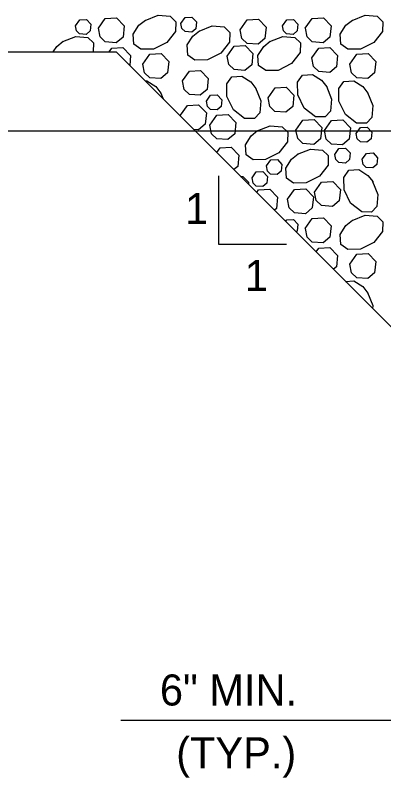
# Model space of a CAD drawing. Extents: x 2084213 to 2099800, y 976677 to 981262.
# Drawn here: x 2094470.4 to 2094587.1, y 978901.8 to 979143.3 of the extents above; entities that cross this region are included whole.
import ezdxf

# ---------------------------------------------------------------- set-up
doc = ezdxf.new("R2010")
doc.units = 0
doc.layers.add('1', color=7, linetype='Continuous')

msp = doc.modelspace()

# ---------------------------------------------------------------- linework, layer by layer
at = {"layer": '1'}
for p, q in [((2094435.37, 979131.66), (2094502.37, 979131.66)), ((2094602.37, 979031.66), (2094502.37, 979131.66)), ((2094326.82, 979106.66), (2094644.86, 979106.66)), ((2094534.73, 979092.4), (2094534.73, 979070.79)), ((2094534.73, 979070.79), (2094556.33, 979070.79)), ((2094503.83, 978919.99), (2095252.37, 978919.99))]:
    msp.add_line(p, q, dxfattribs=at)
for points in [[(2094511.5, 979141.65), (2094515.62, 979143.29), (2094519.41, 979142.96), (2094521.21, 979141.25), (2094521.16, 979138.18), (2094518.42, 979134.68), (2094514.2, 979132.57), (2094510.21, 979132.5), (2094507.97, 979134.09), (2094507.76, 979137.26), (2094509.58, 979140.1), (2094511.66, 979141.76)], [(2094522.88, 979140.68), (2094524.2, 979142.57), (2094526.32, 979142.69), (2094527.78, 979141.16), (2094527.57, 979139.03), (2094526.27, 979137.94), (2094524.18, 979138.1), (2094523.2, 979139.05), (2094522.88, 979140.68)], [(2094577.07, 979141.65), (2094581.2, 979143.29), (2094584.99, 979142.96), (2094586.79, 979141.25), (2094586.74, 979138.18), (2094584, 979134.68), (2094579.78, 979132.57), (2094575.79, 979132.5), (2094573.55, 979134.09), (2094573.34, 979137.26), (2094575.16, 979140.1), (2094577.24, 979141.76)], [(2094489.47, 979139.96), (2094490.79, 979141.84), (2094492.9, 979141.96), (2094494.37, 979140.44), (2094494.16, 979138.31), (2094492.86, 979137.22), (2094490.77, 979137.37), (2094489.79, 979138.32), (2094489.47, 979139.96)], [(2094496.7, 979139.15), (2094498.9, 979142.28), (2094502.42, 979142.49), (2094504.87, 979139.95), (2094504.52, 979136.39), (2094502.34, 979134.58), (2094498.86, 979134.83), (2094497.23, 979136.42), (2094496.7, 979139.15)], [(2094541.66, 979138.67), (2094543.87, 979141.81), (2094547.39, 979142.01), (2094549.84, 979139.47), (2094549.48, 979135.91), (2094547.31, 979134.1), (2094543.83, 979134.36), (2094542.2, 979135.94), (2094541.66, 979138.67)], [(2094555.05, 979139.96), (2094556.37, 979141.84), (2094558.48, 979141.96), (2094559.95, 979140.44), (2094559.74, 979138.31), (2094558.43, 979137.22), (2094556.35, 979137.37), (2094555.37, 979138.32), (2094555.05, 979139.96)], [(2094562.27, 979139.15), (2094564.48, 979142.28), (2094568, 979142.49), (2094570.45, 979139.95), (2094570.09, 979136.39), (2094567.92, 979134.58), (2094564.44, 979134.83), (2094562.81, 979136.42), (2094562.28, 979139.15)], [(2094528.6, 979138.27), (2094532.72, 979139.9), (2094536.51, 979139.58), (2094538.31, 979137.86), (2094538.26, 979134.79), (2094535.52, 979131.29), (2094531.3, 979129.18), (2094527.31, 979129.11), (2094525.07, 979130.7), (2094524.86, 979133.87), (2094526.68, 979136.71), (2094528.76, 979138.37)], [(2094485.43, 979134.93), (2094489.56, 979136.57), (2094493.35, 979136.24), (2094495.15, 979134.53), (2094495.1, 979131.66)], [(2094551.01, 979134.93), (2094555.14, 979136.57), (2094558.93, 979136.24), (2094560.73, 979134.53), (2094560.67, 979131.45), (2094557.94, 979127.96), (2094553.71, 979125.84), (2094549.73, 979125.77), (2094547.49, 979127.37), (2094547.28, 979130.54), (2094549.1, 979133.38), (2094551.18, 979135.04)], [(2094482.41, 979131.66), (2094483.52, 979133.38), (2094485.6, 979135.04)], [(2094500.11, 979131.66), (2094500.98, 979132.89), (2094504.5, 979133.09), (2094506.94, 979130.55), (2094506.63, 979127.4)], [(2094537.51, 979130.37), (2094539.72, 979133.51), (2094543.24, 979133.71), (2094545.69, 979131.17), (2094545.33, 979127.61), (2094543.16, 979125.8), (2094539.68, 979126.06), (2094538.05, 979127.64), (2094537.51, 979130.37)], [(2094564.35, 979129.75), (2094566.55, 979132.89), (2094570.08, 979133.09), (2094572.52, 979130.55), (2094572.17, 979127), (2094569.99, 979125.19), (2094566.52, 979125.44), (2094564.88, 979127.03), (2094564.35, 979129.75)], [(2094510.83, 979127.83), (2094513.03, 979130.97), (2094516.56, 979131.17), (2094519, 979128.63), (2094518.65, 979125.08), (2094516.47, 979123.27), (2094513, 979123.52), (2094511.36, 979125.1), (2094510.83, 979127.83)], [(2094576.41, 979127.83), (2094578.61, 979130.97), (2094582.14, 979131.17), (2094584.58, 979128.63), (2094584.23, 979125.08), (2094582.05, 979123.27), (2094578.58, 979123.52), (2094576.94, 979125.1), (2094576.41, 979127.83)], [(2094523.37, 979122.5), (2094525.58, 979125.63), (2094529.1, 979125.83), (2094531.54, 979123.3), (2094531.19, 979119.74), (2094529.01, 979117.93), (2094525.54, 979118.18), (2094523.9, 979119.77), (2094523.37, 979122.5)], [(2094546.52, 979120.28), (2094548.16, 979116.16), (2094547.83, 979112.37), (2094546.12, 979110.56), (2094543.04, 979110.62), (2094539.55, 979113.35), (2094537.44, 979117.58), (2094537.36, 979121.56), (2094538.96, 979123.8), (2094542.13, 979124.02), (2094544.97, 979122.2), (2094546.63, 979120.11)], [(2094568.94, 979120.82), (2094570.58, 979116.69), (2094570.25, 979112.9), (2094568.53, 979111.1), (2094565.46, 979111.15), (2094561.96, 979113.89), (2094559.85, 979118.11), (2094559.78, 979122.1), (2094561.37, 979124.34), (2094564.55, 979124.55), (2094567.38, 979122.73), (2094569.04, 979120.65)], [(2094511.52, 979122.51), (2094512.04, 979122.55), (2094514.88, 979120.73), (2094516.54, 979118.65)], [(2094582.02, 979118.81), (2094583.65, 979114.69), (2094583.32, 979110.9), (2094581.61, 979109.1), (2094578.54, 979109.15), (2094575.04, 979111.89), (2094572.93, 979116.11), (2094572.86, 979120.09), (2094574.45, 979122.34), (2094577.62, 979122.55), (2094580.46, 979120.73), (2094582.12, 979118.65)], [(2094516.44, 979118.81), (2094517.24, 979116.79)], [(2094550.48, 979117.16), (2094552.69, 979120.3), (2094556.21, 979120.5), (2094558.66, 979117.96), (2094558.31, 979114.4), (2094556.13, 979112.59), (2094552.65, 979112.85), (2094551.02, 979114.43), (2094550.49, 979117.16)], [(2094530.95, 979116.07), (2094532.27, 979117.95), (2094534.38, 979118.07), (2094535.85, 979116.55), (2094535.64, 979114.41), (2094534.33, 979113.33), (2094532.25, 979113.48), (2094531.27, 979114.43), (2094530.95, 979116.07)], [(2094522.75, 979111.6), (2094524.96, 979114.74), (2094528.48, 979114.94), (2094530.93, 979112.4), (2094530.57, 979108.84), (2094528.4, 979107.04), (2094526.88, 979107.15)], [(2094522.83, 979111.2), (2094522.75, 979111.6)], [(2094532.07, 979108.49), (2094534.28, 979111.62), (2094537.8, 979111.83), (2094540.25, 979109.29), (2094539.89, 979105.73), (2094537.72, 979103.92), (2094534.24, 979104.17), (2094532.6, 979105.76), (2094532.07, 979108.49)], [(2094559.31, 979106.93), (2094561.52, 979110.07), (2094565.04, 979110.27), (2094567.49, 979107.73), (2094567.13, 979104.18), (2094564.96, 979102.37), (2094561.48, 979102.62), (2094559.85, 979104.2), (2094559.31, 979106.93)], [(2094568.39, 979106.8), (2094570.59, 979109.94), (2094574.11, 979110.14), (2094576.56, 979107.6), (2094576.21, 979104.04), (2094574.03, 979102.23), (2094570.55, 979102.49), (2094568.92, 979104.07), (2094568.39, 979106.8)], [(2094547.01, 979106.65), (2094551.13, 979108.28), (2094554.93, 979107.95), (2094556.73, 979106.24), (2094556.67, 979103.16), (2094553.93, 979099.67), (2094549.71, 979097.56), (2094545.73, 979097.49), (2094543.49, 979099.08), (2094543.27, 979102.25), (2094545.09, 979105.09), (2094547.17, 979106.75)], [(2094578.42, 979105.83), (2094579.74, 979107.71), (2094581.86, 979107.83), (2094583.33, 979106.31), (2094583.11, 979104.18), (2094581.81, 979103.09), (2094579.72, 979103.24), (2094578.74, 979104.19), (2094578.42, 979105.83)], [(2094534.21, 979099.82), (2094535.26, 979101.3), (2094538.78, 979101.5), (2094541.23, 979098.96), (2094540.87, 979095.41), (2094539.64, 979094.39)], [(2094559.81, 979099.27), (2094563.94, 979100.91), (2094567.73, 979100.58), (2094569.53, 979098.87), (2094569.47, 979095.79), (2094566.74, 979092.3), (2094562.51, 979090.19), (2094558.53, 979090.12), (2094556.29, 979091.71), (2094556.08, 979094.88), (2094557.89, 979097.72), (2094559.98, 979099.38)], [(2094571.59, 979099.21), (2094572.92, 979101.09), (2094575.03, 979101.21), (2094576.5, 979099.69), (2094576.29, 979097.56), (2094574.98, 979096.47), (2094572.89, 979096.62), (2094571.91, 979097.57), (2094571.6, 979099.21)], [(2094580.28, 979097.66), (2094581.61, 979099.54), (2094583.72, 979099.66), (2094585.19, 979098.14), (2094584.97, 979096.01), (2094583.67, 979094.92), (2094581.58, 979095.07), (2094580.6, 979096.02), (2094580.28, 979097.66)], [(2094549.98, 979095.59), (2094551.3, 979097.47), (2094553.41, 979097.59), (2094554.88, 979096.07), (2094554.67, 979093.94), (2094553.37, 979092.85), (2094551.28, 979093), (2094550.3, 979093.95), (2094549.98, 979095.59)], [(2094583.61, 979090.66), (2094585.25, 979086.53), (2094584.92, 979082.74), (2094583.21, 979080.94), (2094580.14, 979081), (2094576.64, 979083.73), (2094574.53, 979087.96), (2094574.46, 979091.94), (2094576.05, 979094.18), (2094579.22, 979094.39), (2094582.06, 979092.58), (2094583.72, 979090.49)], [(2094541.79, 979092.24), (2094542.51, 979092.18), (2094544.31, 979090.46), (2094544.3, 979089.73)], [(2094545.43, 979091.76), (2094546.75, 979093.65), (2094548.86, 979093.77), (2094550.33, 979092.24), (2094550.12, 979090.11), (2094548.81, 979089.02), (2094546.73, 979089.17), (2094545.75, 979090.13), (2094545.43, 979091.76)], [(2094565.21, 979087.3), (2094567.42, 979090.44), (2094570.94, 979090.64), (2094573.39, 979088.1), (2094573.04, 979084.54), (2094570.86, 979082.73), (2094567.38, 979082.99), (2094565.75, 979084.57), (2094565.22, 979087.3)], [(2094546.88, 979087.15), (2094547.49, 979088.01), (2094551.01, 979088.21), (2094553.46, 979085.67), (2094553.1, 979082.11), (2094552.46, 979081.57)], [(2094556.66, 979085), (2094558.87, 979088.13), (2094562.39, 979088.34), (2094564.84, 979085.8), (2094564.48, 979082.24), (2094562.31, 979080.43), (2094558.83, 979080.68), (2094557.19, 979082.27), (2094556.66, 979085)], [(2094577.07, 979078.29), (2094581.2, 979079.92), (2094584.99, 979079.6), (2094586.79, 979077.88), (2094586.74, 979074.81), (2094584, 979071.31), (2094579.78, 979069.2), (2094575.79, 979069.13), (2094573.55, 979070.72), (2094573.34, 979073.89), (2094575.16, 979076.73), (2094577.24, 979078.39)], [(2094556.03, 979078), (2094556.37, 979078.47), (2094558.48, 979078.6), (2094559.95, 979077.07), (2094559.74, 979074.94), (2094559.38, 979074.64)], [(2094562.27, 979075.78), (2094564.48, 979078.92), (2094568, 979079.12), (2094570.45, 979076.58), (2094570.09, 979073.02), (2094567.92, 979071.21), (2094564.44, 979071.46), (2094562.81, 979073.05), (2094562.28, 979075.78)], [(2094565.71, 979068.32), (2094566.55, 979069.52), (2094570.08, 979069.72), (2094572.52, 979067.19), (2094572.17, 979063.63), (2094571.2, 979062.83)], [(2094576.41, 979064.47), (2094578.61, 979067.6), (2094582.14, 979067.8), (2094584.58, 979065.27), (2094584.23, 979061.71), (2094582.05, 979059.9), (2094578.58, 979060.15), (2094576.94, 979061.74), (2094576.41, 979064.46)], [(2094575.02, 979059.01), (2094577.62, 979059.18), (2094580.46, 979057.36), (2094582.12, 979055.28)], [(2094582.02, 979055.45), (2094583.65, 979051.32), (2094583.58, 979050.45)]]:
    msp.add_lwpolyline(points, dxfattribs=at)

# ---------------------------------------------------------------- texts
for s, height, p in [('1', 9.84, (2094524.18, 979077.13)), ('1', 9.84, (2094543.11, 979055.94)), ('6" MIN.', 9.843, (2094516.21, 978924.66)), ('(TYP.)', 9.843, (2094521.36, 978904.74))]:
    msp.add_text(s, height=height, dxfattribs=at).set_placement(p)

doc.saveas('drawing.dxf')
